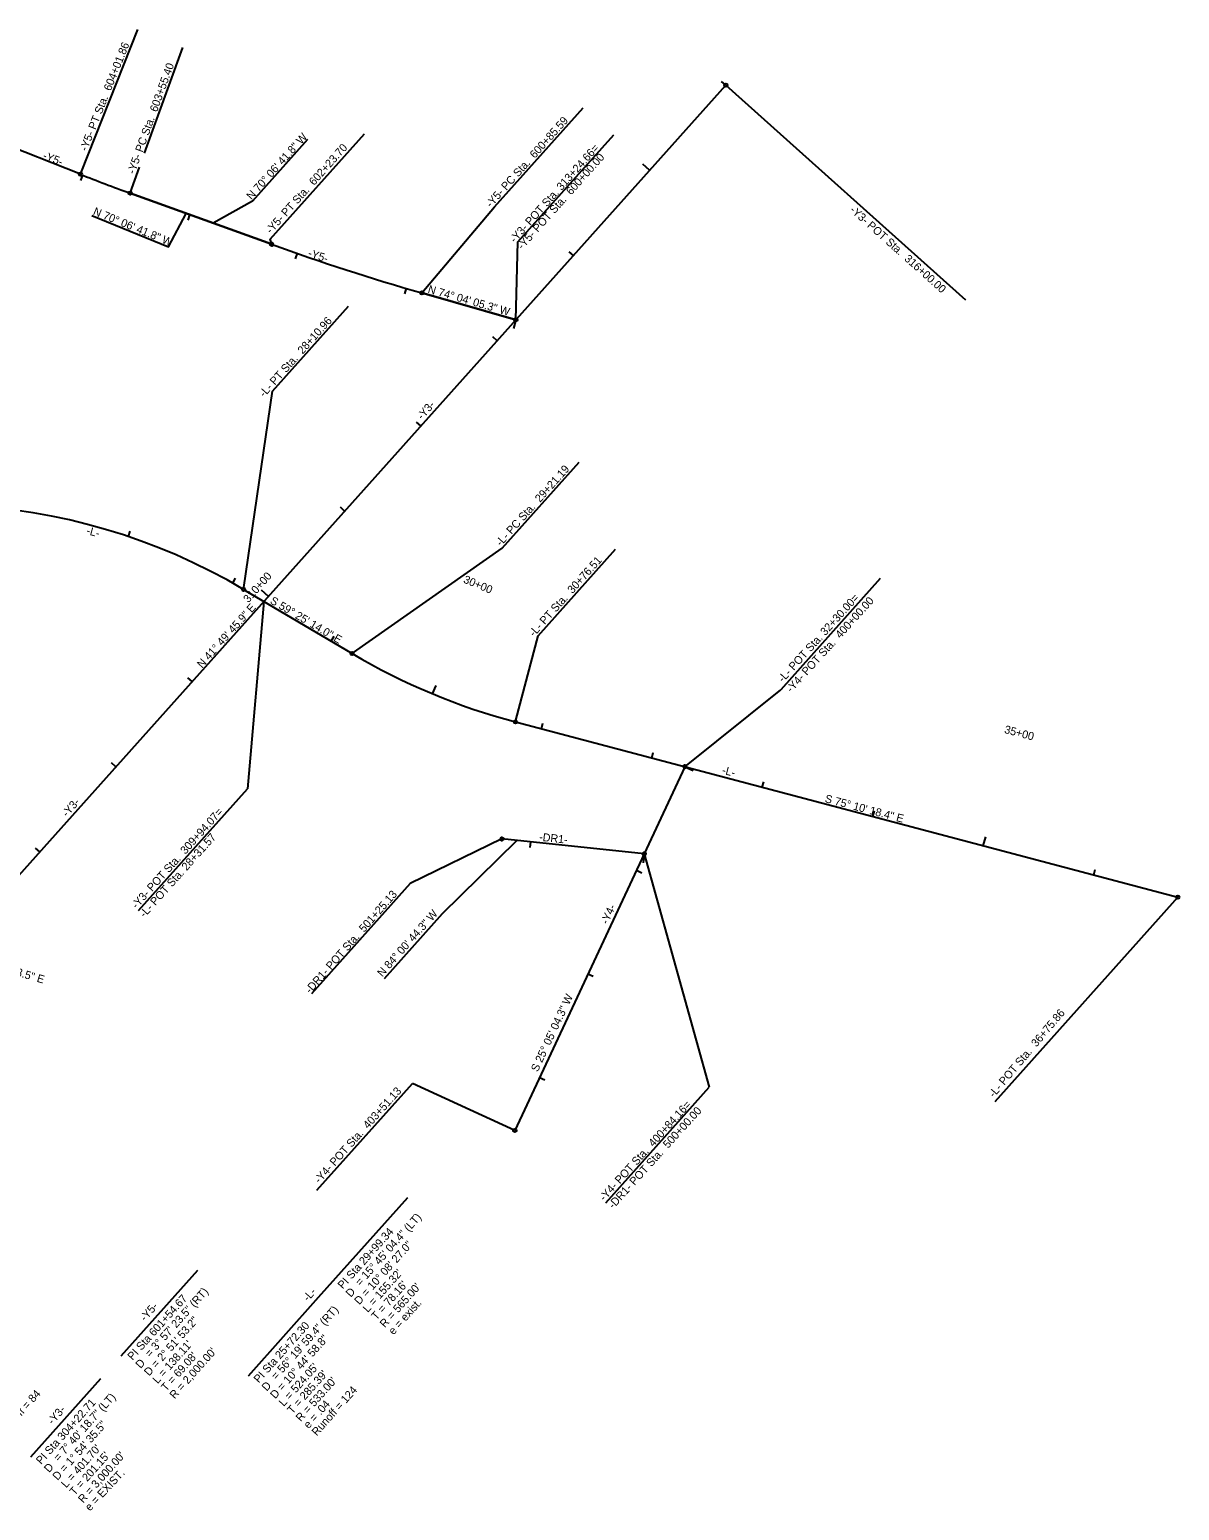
# Model space of a CAD drawing. Extents: x 2090177 to 2092717, y 863117 to 864817.
# Drawn here: x 2091711 to 2092717, y 863117 to 864412 of the extents above; entities that cross this region are included whole.
import ezdxf

# ---------------------------------------------------------------- set-up
doc = ezdxf.new("R2010")
doc.units = 0
for name, color, linetype in [('Prop Horizontal Alignment', 7, 'Continuous'), ('Prop Horizontal Alignment Curve and Spiral Data', 7, 'Continuous'), ('Prop Horizontal Alignment Direction Label', 7, 'Continuous'), ('Prop Horizontal Alignment Point', 7, 'Continuous'), ('Prop Horizontal Alignment Station Label', 7, 'Continuous'), ('Prop Horizontal Alignment Tick Label', 7, 'Continuous'), ('Prop Horizontal Alignment Tick Large', 7, 'Continuous'), ('Prop Horizontal Alignment Tick Small', 7, 'Continuous')]:
    doc.layers.add(name, color=color, linetype=linetype)

msp = doc.modelspace()

# ---------------------------------------------------------------- linework, layer by layer
at = {"layer": 'Prop Horizontal Alignment'}
for p, q in [((2091668.6, 863635.4), (2092320, 864363.2)), ((2091755.4, 864285.3), (2091585.5, 864352.7)), ((2091755.4, 864285.3), (2091585.5, 864352.7)), ((2091798.8, 864268.8), (2091922.7, 864224)), ((2091922.7, 864224), (2091798.8, 864268.8)), ((2092054, 864181.5), (2092136.3, 864158)), ((2092136.3, 864158), (2092054, 864181.5)), ((2091898.1, 863922.2), (2091993, 863866.1)), ((2092135.9, 863806.3), (2092715.3, 863653)), ((2092284.2, 863767.1), (2092135.4, 863449)), ((2092248.6, 863690.8), (2092124.1, 863703.9))]:
    msp.add_line(p, q, dxfattribs=at)
for centre, radius, start, end in [((2092309.1, 865679.3), 1500, 248.3371, 250.1116), ((2092309.1, 865679.3), 1500, 248.3371, 250.1116), ((2092603, 866104.7), 2000, 250.1116, 254.0681), ((2092603, 866104.7), 2000, 250.1116, 254.0681), ((2091627, 863463.3), 533, 59.4206, 115.7537), ((2092280.5, 864352.5), 565, 239.4206, 255.1718)]:
    msp.add_arc(centre, radius, start, end, dxfattribs=at)
at = {"layer": 'Prop Horizontal Alignment Curve and Spiral Data'}
for p, q in [((2091963.7, 863303.1), (2092041.7, 863390.3)), ((2091790.9, 863251.8), (2091858, 863326.8)), ((2091902.3, 863234.5), (2091963.7, 863303.1)), ((2091711.9, 863163.6), (2091773.2, 863232))]:
    msp.add_line(p, q, dxfattribs=at)
at = {"layer": 'Prop Horizontal Alignment Station Label'}
for p, q in [((2091755.9, 864286.7), (2091805.6, 864411.8)), ((2091811.4, 864303.6), (2091844.9, 864396.2)), ((2092320, 864363.2), (2092529.7, 864175.4)), ((2091798.8, 864268.8), (2091807.1, 864291.6)), ((2092455.1, 863931.7), (2092368, 863834.3)), ((2091915.9, 863911.7), (2091901.5, 863747.8)), ((2092284.2, 863767.1), (2092368, 863834.3)), ((2091806.1, 863641.2), (2091901.5, 863747.8)), ((2092124.1, 863703.9), (2092043.9, 863665)), ((2092071.9, 863638.5), (2092137.1, 863702.5)), ((2092248.6, 863690.8), (2092305.5, 863486.8)), ((2092043.9, 863665), (2091957.5, 863568.4)), ((2092715.3, 863653), (2092555.2, 863474.1)), ((2092071.9, 863638.5), (2092021, 863581.7)), ((2091962.1, 863396.7), (2092045.8, 863490.1)), ((2092135.4, 863449), (2092045.8, 863490.1)), ((2092215, 863385.6), (2092305.5, 863486.8))]:
    msp.add_line(p, q, dxfattribs=at)
for points in [[(2092054, 864181.5), (2092117.7, 864256.9), (2092195.1, 864343.3)], [(2091954.1, 864315.6), (2091905.9, 864261.8), (2091871.6, 864242.4)], [(2091922.7, 864224), (2091921.5, 864228.6), (2092003.9, 864320.7)], [(2092136.3, 864158), (2092138, 864226.1), (2092222, 864319.8)], [(2091765.5, 864249.3), (2091832.4, 864221.8), (2091847.9, 864251)], [(2091898.3, 863923.7), (2091923.4, 864095.6), (2091990, 864170)], [(2091994.3, 863867), (2092124.3, 863958.1), (2092191.7, 864033.5)], [(2092136.2, 863807.8), (2092155.8, 863881.5), (2092223.6, 863957.3)]]:
    msp.add_lwpolyline(points, dxfattribs=at)
for centre in [(2092320, 864363.2), (2091755.4, 864285.3), (2091798.8, 864268.8), (2091922.7, 864224), (2092054, 864181.5), (2092136.3, 864158), (2091898.1, 863922.2), (2091993, 863866.1), (2092135.9, 863806.3), (2092284.2, 863767.1), (2092284.2, 863767.1), (2092124.1, 863703.9), (2092124.1, 863703.9), (2092248.6, 863690.8), (2092715.3, 863653), (2092135.4, 863449)]:
    msp.add_circle(centre, 1.5, dxfattribs=at)
at = {"layer": 'Prop Horizontal Alignment Tick Large'}
for p, q in [((2092253.3, 864288.7), (2092247.3, 864294)), ((2092136.3, 864158), (2092134.2, 864150.3)), ((2091919.8, 863916.1), (2091913.9, 863921.4)), ((2092063.4, 863830.9), (2092066.5, 863838.2)), ((2092284.2, 863767.1), (2092291.5, 863763.7)), ((2092284.2, 863767.1), (2092291.5, 863763.7)), ((2092545.2, 863698), (2092547.3, 863705.7)), ((2092248.6, 863690.8), (2092247.7, 863682.9))]:
    msp.add_line(p, q, dxfattribs=at)
at = {"layer": 'Prop Horizontal Alignment Tick Small'}
for p, q in [((2092320, 864363.2), (2092316.3, 864366.5)), ((2091757.1, 864284.6), (2091755.3, 864279.9)), ((2091850.9, 864249.9), (2091849.2, 864245.2)), ((2091945, 864216.1), (2091943.3, 864211.3)), ((2092186.6, 864214.2), (2092182.9, 864217.5)), ((2092040.2, 864185.5), (2092038.8, 864180.7)), ((2092119.9, 864139.6), (2092116.2, 864143)), ((2092053.2, 864065.1), (2092049.5, 864068.5)), ((2091986.5, 863990.6), (2091982.8, 863994)), ((2091797.4, 863968.3), (2091799, 863973)), ((2091888.6, 863927.7), (2091891.1, 863932)), ((2091974.8, 863876.9), (2091977.3, 863881.2)), ((2091853.1, 863841.6), (2091849.4, 863844.9)), ((2092158.6, 863800.3), (2092159.8, 863805.2)), ((2092255.2, 863774.7), (2092256.5, 863779.6)), ((2091786.4, 863767.1), (2091782.7, 863770.4)), ((2092351.9, 863749.1), (2092353.2, 863754)), ((2092448.6, 863723.6), (2092449.9, 863728.4)), ((2091719.8, 863692.6), (2091716, 863695.9)), ((2092149.1, 863701.3), (2092148.6, 863696.3)), ((2092241.8, 863676.5), (2092246.4, 863674.4)), ((2092641.9, 863672.4), (2092643.2, 863677.2)), ((2092199.4, 863585.9), (2092204, 863583.8)), ((2092157.1, 863495.4), (2092161.6, 863493.2))]:
    msp.add_line(p, q, dxfattribs=at)

# ---------------------------------------------------------------- texts
at = {"layer": 'Prop Horizontal Alignment Curve and Spiral Data'}
for s, rotation, p in [('= 15%%d 45\' 04.4" (LT)', 48.2166, (2092000.3, 863312.4)), ('PI Sta 29+99.34', 48.2166, (2091984.9, 863309.8)), ('D = 10%%d 08\' 27.0"', 48.2166, (2091999.4, 863296)), ("L = 155.32'", 48.2166, (2092006.8, 863289.3)), ("T = 78.16'", 48.2166, (2092014.3, 863282.6)), ("R = 565.00'", 48.2166, (2092021.7, 863276)), ('PI Sta 601+54.67', 48.1734, (2091801, 863247.5)), ('= 3%%d 57\' 23.5" (RT)', 48.1734, (2091816.3, 863250.1)), ('-L-', 48.7377, (2091954.5, 863299)), ('D', 48.2166, (2091991.9, 863302.6)), ('-Y5-', 48.7377, (2091812, 863281.5)), ('= 56%%d 19\' 59.4" (RT)', 48.2242, (2091926.7, 863230.3)), ('e = exist.', 48.2242, (2092029.3, 863269.7)), ('D = 2%%d 51\' 53.2"', 48.1734, (2091815.5, 863233.7)), ('PI Sta 25+72.30', 48.2242, (2091911.4, 863227.6)), ("L = 138.11'", 48.1734, (2091822.9, 863227)), ('D = 10%%d 44\' 58.8"', 48.2242, (2091925.8, 863213.8)), ('D', 48.1734, (2091808, 863240.3)), ("T = 69.08'", 48.1734, (2091830.4, 863220.3)), ("R = 2,000.00'", 48.1734, (2091837.8, 863213.7)), ("L = 524.05'", 48.2242, (2091933.3, 863207.1)), ("T = 285.39'", 48.2242, (2091940.8, 863200.5)), ('D', 48.2242, (2091918.4, 863220.5)), ("R = 533.00'", 48.2242, (2091948.2, 863193.8)), ('Runoff = 124', 48.2242, (2091962.2, 863181.3)), ('Runoff = 84', 48.2242, (2091688.7, 863182)), ('PI Sta 304+22.71', 48.221, (2091721, 863156.4)), ('= 7%%d 40\' 18.7" (LT)', 48.221, (2091736.3, 863159)), ('e = .04', 48.2242, (2091955, 863187.7)), ('-Y3-', 48.7377, (2091731.1, 863191.2)), ('D = 1%%d 54\' 35.5"', 48.221, (2091735.4, 863142.5)), ("L = 401.70'", 48.221, (2091742.9, 863135.9)), ("T = 201.15'", 48.221, (2091750.4, 863129.2)), ("R = 3,000.00'", 48.221, (2091757.8, 863122.6)), ('D', 48.221, (2091728, 863149.2)), ('e = EXIST.', 46.9938, (2091763.7, 863115.6))]:
    msp.add_text(s, height=7, rotation=rotation, dxfattribs=at).set_placement(p)
at = {"layer": 'Prop Horizontal Alignment Direction Label'}
for s, rotation, p in [('N 70%%d 06\' 41.8" W', 48.1706, (2091905.1, 864262.4)), ('N 70%%d 06\' 41.8" W', 337.6724, (2091765.9, 864250.2)), ('N 74%%d 04\' 05.3" W', 344.0681, (2092058.8, 864181.7)), ('N 41%%d 49\' 45.9" E', 48.1706, (2091861.8, 863852.8)), ('S 59%%d 25\' 14.0" E', 329.4206, (2091920.6, 863910.4)), ('S 75%%d 10\' 18.4" E', 345.1718, (2092406.1, 863736.2)), ('N 84%%d 00\' 44.3" W', 48.5081, (2092019.5, 863582.8)), ('S 73%%d 39\' 23.5" E', 343.6565, (2091654.8, 863597.3)), ('S 25%%d 05\' 04.3" W', 64.9155, (2092155.4, 863499.7))]:
    msp.add_text(s, height=7, rotation=rotation, dxfattribs=at).set_placement(p)
at = {"layer": 'Prop Horizontal Alignment Point'}
for s, rotation, p in [('-Y5-', 338.3371, (2091721.9, 864299)), ('-Y5-', 341.8835, (2091953.9, 864213.5)), ('-Y3-', 48.3751, (2092054.2, 864070)), ('-L-', 344.6294, (2091760.1, 863970.7)), ('-L-', 345.7007, (2092316.2, 863761.1)), ('-Y3-', 48.3751, (2091743.6, 863722.6)), ('-DR1-', 354.0123, (2092156.4, 863702.4)), ('-Y4-', 65.3652, (2092216.6, 863628.7))]:
    msp.add_text(s, height=7, rotation=rotation, dxfattribs=at).set_placement(p)
at = {"layer": 'Prop Horizontal Alignment Station Label'}
for s, rotation, p in [('-Y5- PT Sta.  604+01.86', 68.3371, (2091761, 864304.9)), ('-Y5- PC Sta.  603+55.40', 70.1116, (2091802.7, 864284.9)), ('-Y5- PC Sta.  600+85.59', 48.1706, (2092114.4, 864255.6)), ('-Y5- PT Sta.  602+23.70', 48.1706, (2091922, 864232.7)), ('-Y3- POT Sta. 313+24.66=', 48.1706, (2092135.4, 864224.8)), ('-Y5- POT Sta.  600+00.00', 48.1706, (2092142, 864218.9)), ('-Y3- POT Sta.  316+00.00', 318.1706, (2092427.9, 864253.2)), (' -L- PT Sta.  28+10.96', 48.1706, (2091914.4, 864087.9)), ('-L- PC Sta.  29+21.19', 48.1706, (2092123.1, 863959.4)), ('-L- PT Sta.  30+76.51', 48.1706, (2092152.2, 863880.4)), ('-L- POT Sta. 32+30.00=', 47.8197, (2092370, 863840.4)), ('-Y4- POT Sta.  400+00.00', 47.8197, (2092377.2, 863831.4)), ('-Y3- POT Sta.  309+94.07=', 48.0802, (2091804.5, 863642.4)), ('-L- POT Sta. 28+31.57', 48.0802, (2091811.5, 863634.7)), ('-DR1- POT Sta.  501+25.13', 48.688, (2091956.5, 863568.2)), ('-L- POT Sta.  36+75.86', 49.8629, (2092554.5, 863477.3)), ('-Y4- POT Sta.  403+51.13', 48.1706, (2091964.4, 863402.2)), ('-Y4- POT Sta.  400+84.16=', 47.8197, (2092213.7, 863386.7)), ('-DR1- POT Sta.  500+00.00', 47.8197, (2092221.6, 863380))]:
    msp.add_text(s, height=7, rotation=rotation, dxfattribs=at).set_placement(p)
at = {"layer": 'Prop Horizontal Alignment Tick Label'}
for s, rotation, p in [('310+00', 48.1706, (2091902.3, 863910)), ('30+00', 337.413, (2092089.8, 863928.3)), ('35+00', 345.1718, (2092563.1, 863796.7))]:
    msp.add_text(s, height=7, rotation=rotation, dxfattribs=at).set_placement(p)

doc.saveas('drawing.dxf')
